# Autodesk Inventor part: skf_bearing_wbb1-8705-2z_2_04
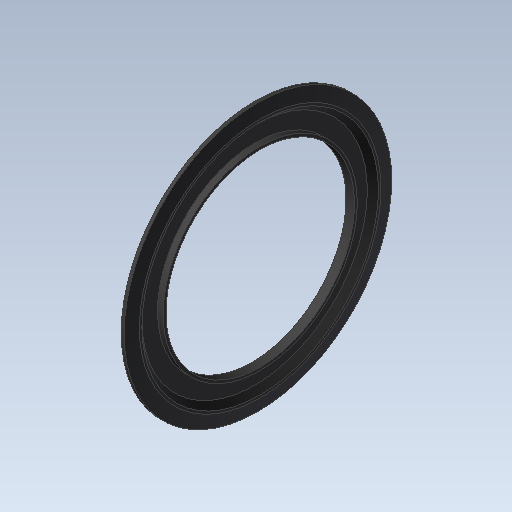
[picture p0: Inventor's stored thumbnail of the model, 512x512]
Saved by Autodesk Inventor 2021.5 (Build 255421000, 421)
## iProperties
Created: 2023-11
Part Number: skf_bearing_wbb1-8705-2z_2_04
Checked By: TraceParts S.A.
Material: Generic
Catalog Web Link: www.traceparts.com
Document SubType Name: Modeling
Designer: TraceParts
Density: 1 g/cm^3
Appearance: Default
Company: TraceParts S.A.
Author: TraceParts
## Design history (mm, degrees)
feature "skf_bearing_wbb1-8705-2z_2_04.ipt"
body "Solid1"
